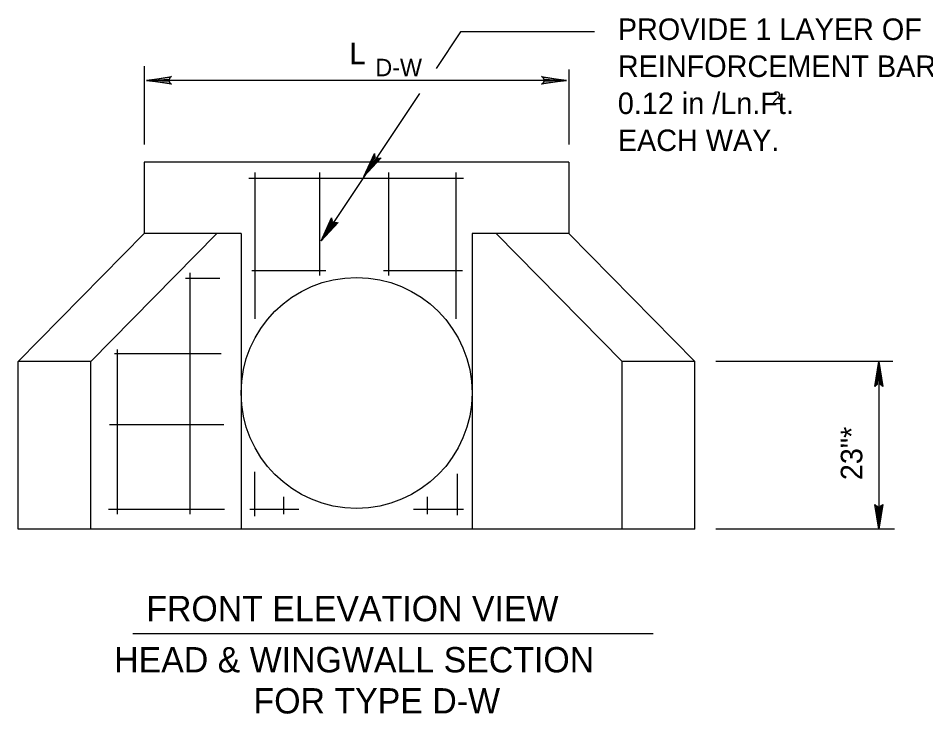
# Model space of a CAD drawing. Extents: x 638877 to 639960, y 297341 to 299123.
# Drawn here: x 638967.5 to 639093.9, y 297659.2 to 297756.2 of the extents above; entities that cross this region are included whole.
import ezdxf

# ---------------------------------------------------------------- set-up
doc = ezdxf.new("R2010")
doc.units = 0
for name, color, linetype in [('1', 7, 'Continuous'), ('2', 7, 'Continuous'), ('3', 7, 'Continuous')]:
    doc.layers.add(name, color=color, linetype=linetype)

msp = doc.modelspace()

# ---------------------------------------------------------------- linework, layer by layer
at = {"layer": '2'}
for p, q in [((639029.09, 297754.28), (639025.69, 297749.17)), ((639047.77, 297754.28), (639029.09, 297754.28)), ((638985.01, 297749.47), (638985.01, 297738.56)), ((639044.2, 297749.01), (639044.2, 297738.56)), ((639043.86, 297747.51), (638985.36, 297747.51)), ((639023.37, 297745.7), (639009.8, 297725.33)), ((639044.2, 297736.12), (638985.01, 297736.12)), ((638985.01, 297736.12), (638985.01, 297726.19)), ((639044.2, 297736.12), (639044.2, 297726.19)), ((639000.49, 297714.28), (639000.49, 297734.66)), ((639009.47, 297720.98), (639009.47, 297734.66)), ((639019.12, 297720.31), (639019.12, 297734.66)), ((639028.5, 297714.28), (639028.5, 297734.66)), ((639029.5, 297733.82), (638999.61, 297733.82)), ((638985.01, 297726.19), (638967.46, 297708.34)), ((638995.09, 297726.13), (638977.6, 297708.34)), ((638998.52, 297726.19), (638985.01, 297726.19)), ((638998.52, 297726.19), (638998.52, 297684.94)), ((639030.7, 297726.19), (639030.7, 297684.94)), ((639044.2, 297726.19), (639030.7, 297726.19)), ((639051.62, 297708.34), (639034.12, 297726.13)), ((639061.75, 297708.34), (639044.2, 297726.19)), ((638991.45, 297687.05), (638991.45, 297720.71)), ((639010.33, 297720.95), (639000.01, 297720.95)), ((639009.47, 297720.31), (639009.47, 297720.98)), ((639029.37, 297720.95), (639018.38, 297720.95)), ((638995.56, 297719.88), (638990.76, 297719.88)), ((638995.73, 297709.41), (638980.87, 297709.41)), ((638981.32, 297687.05), (638981.32, 297709.99)), ((638967.46, 297684.94), (638967.46, 297708.34)), ((638977.6, 297708.34), (638967.47, 297708.34)), ((638977.6, 297684.94), (638977.6, 297708.34)), ((639061.75, 297708.34), (639051.63, 297708.34)), ((639051.63, 297684.94), (639051.63, 297708.34)), ((639061.75, 297684.94), (639061.75, 297708.34)), ((639089.32, 297708.34), (639064.65, 297708.34)), ((639087.38, 297708.34), (639087.38, 297684.94)), ((638996.13, 297699.49), (638980.17, 297699.49)), ((639000.45, 297686.78), (639000.45, 297692.96)), ((639028.66, 297686.92), (639028.66, 297692.69)), ((639004.49, 297687.05), (639004.49, 297689.47)), ((639024.47, 297687.05), (639024.47, 297689.47)), ((638996.19, 297687.69), (638980.06, 297687.69)), ((639006.58, 297687.69), (638999.74, 297687.69)), ((639014.61, 297687.86), (639014.61, 297687.86)), ((639029.5, 297687.69), (639022.53, 297687.69)), ((639061.75, 297684.94), (638967.46, 297684.94)), ((639051.63, 297684.94), (638977.6, 297684.94)), ((639014.61, 297684.94), (639014.61, 297684.94)), ((639089.55, 297684.94), (639064.65, 297684.94))]:
    msp.add_line(p, q, dxfattribs=at)
for points in [[(638988.66, 297747.1), (638988.54, 297747.34), (638985.36, 297747.51), (638988.66, 297747.1), (638988.84, 297746.96), (638985.36, 297747.51), (638988.54, 297747.67), (638988.66, 297747.91), (638985.36, 297747.51), (638988.84, 297748.07), (638988.66, 297747.91)], [(639040.55, 297747.93), (639040.68, 297747.69), (639043.86, 297747.51), (639040.55, 297747.93), (639040.38, 297748.07), (639043.86, 297747.51), (639040.68, 297747.36), (639040.56, 297747.12), (639043.86, 297747.51), (639040.38, 297746.96), (639040.56, 297747.12)], [(639017.81, 297736.64), (639017.54, 297736.67), (639015.63, 297734.11), (639017.81, 297736.64), (639018.02, 297736.7), (639015.63, 297734.11), (639017.26, 297736.85), (639017.13, 297737.08), (639015.63, 297734.11), (639017.1, 297737.31), (639017.13, 297737.08)], [(639011.85, 297727.65), (639011.58, 297727.68), (639009.67, 297725.13), (639011.85, 297727.65), (639012.06, 297727.71), (639009.67, 297725.13), (639011.3, 297727.86), (639011.17, 297728.09), (639009.67, 297725.13), (639011.14, 297728.33), (639011.17, 297728.09)], [(639086.96, 297705.04), (639087.2, 297705.16), (639087.38, 297708.34), (639086.96, 297705.04), (639086.82, 297704.86), (639087.38, 297708.34), (639087.54, 297705.16), (639087.78, 297705.04), (639087.38, 297708.34), (639087.93, 297704.86), (639087.78, 297705.04)], [(639087.8, 297688.24), (639087.56, 297688.12), (639087.38, 297684.94), (639087.8, 297688.24), (639087.94, 297688.41), (639087.38, 297684.94), (639087.22, 297688.12), (639086.99, 297688.23), (639087.38, 297684.94), (639086.83, 297688.41), (639086.99, 297688.23)]]:
    msp.add_lwpolyline(points, dxfattribs=at)
msp.add_circle((639014.61, 297703.95), 16.09, dxfattribs=at)
at = {"layer": '3'}
msp.add_line((638983.44, 297670.42), (639055.95, 297670.42), dxfattribs=at)

# ---------------------------------------------------------------- texts
at = {"layer": '1'}
for s, height, p in [('D-W', 2.43, (639017.23, 297748.09)), ('2', 1.8, (639072.45, 297744.17))]:
    msp.add_text(s, height=height, dxfattribs=at).set_placement(p)
for s, p in [('HEAD & WINGWALL SECTION', (638980.84, 297665)), ('FOR TYPE D-W', (639000.25, 297659.27))]:
    msp.add_text(s, height=3.5299, rotation=360, dxfattribs=at).set_placement(p)
at = {"layer": '3'}
for s, height, p in [('PROVIDE 1 LAYER OF', 2.9999, (639051.01, 297753.14)), ('L', 3, (639013.62, 297749.77)), ('REINFORCEMENT BARS', 2.9999, (639051.01, 297747.98)), ('0.12 in /Ln.Ft.', 2.9999, (639051.01, 297742.82)), ('EACH WAY.', 3, (639051.01, 297737.66)), ('FRONT ELEVATION VIEW', 3.5299, (638985.31, 297672.13))]:
    msp.add_text(s, height=height, dxfattribs=at).set_placement(p)
msp.add_text('23"*', height=3, rotation=90, dxfattribs=at).set_placement((639085.07, 297691.79))

doc.saveas('drawing.dxf')
